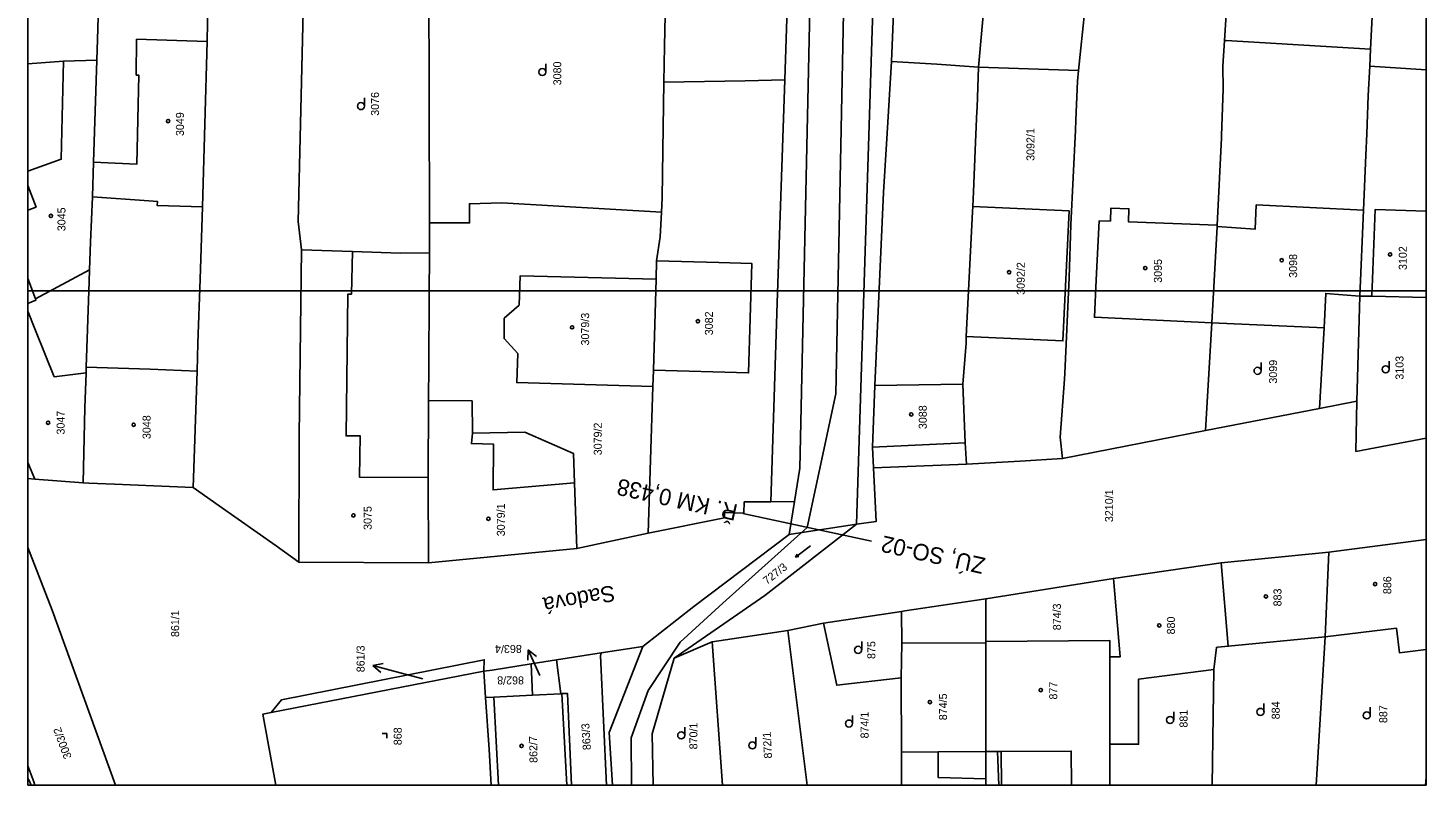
# Model space of a CAD drawing. Extents: x -534410 to -534262, y -1190162 to -1189584.
# Drawn here: x -534410.1 to -534261.6, y -1190162 to -1190081.5 of the extents above; entities that cross this region are included whole.
import ezdxf

# ---------------------------------------------------------------- set-up
doc = ezdxf.new("R2010")
doc.units = 0
for name, color, linetype in [('_KN_Povodí_Moravy', 7, 'Continuous'), ('_N_osa', 7, 'Continuous'), ('_N_tenká', 7, 'Continuous'), ('_N_text', 7, 'Continuous'), ('_rámeček', 7, 'Continuous'), ('_rámeček_mřížka', 7, 'Continuous'), ('_tenka', 7, 'Continuous'), ('Hranice parcel', 7, 'Continuous'), ('Parcelní čísla', 7, 'Continuous'), ('Polygon budovy', 7, 'Continuous'), ('Pop  PČ popisy', 7, 'Continuous'), ('Značky budov', 7, 'Continuous'), ('Značky kultur', 7, 'Continuous')]:
    doc.layers.add(name, color=color, linetype=linetype)

msp = doc.modelspace()

# ---------------------------------------------------------------- linework, layer by layer
at = {"layer": '_KN_Povodí_Moravy'}
for p, q in [((-534328.71, -1190131.86), (-534329.29, -1190135.36)), ((-534329.29, -1190135.36), (-534326.31, -1190134.9)), ((-534326.31, -1190134.9), (-534325.09, -1190134.72)), ((-534325.09, -1190134.72), (-534322.11, -1190134.26)), ((-534348.05, -1190161.97), (-534343.71, -1190161.97))]:
    msp.add_line(p, q, dxfattribs=at)
for points in [[(-534333.99, -1189993.03), (-534331.98, -1189997.67), (-534327.34, -1190013.08), (-534325.48, -1190021.81), (-534326.93, -1190073), (-534328.13, -1190128.3), (-534328.71, -1190131.86)], [(-534322.11, -1190134.26), (-534321.95, -1190128.7), (-534320.16, -1190072.85), (-534318.8, -1190033.53)], [(-534329.29, -1190135.36), (-534339.41, -1190143.01), (-534344.83, -1190147.24)], [(-534341.5, -1190148.5), (-534331.87, -1190141.82), (-534322.11, -1190134.26)], [(-534322.11, -1190134.26), (-534325.09, -1190134.72), (-534326.31, -1190134.9), (-534329.29, -1190135.36)], [(-534344.83, -1190147.24), (-534348.39, -1190156.38), (-534348.05, -1190161.97)], [(-534343.71, -1190161.97), (-534343.82, -1190156.54), (-534341.5, -1190148.5)]]:
    msp.add_lwpolyline(points, dxfattribs=at)
at = {"layer": '_N_osa'}
for points in [[(-534327.36, -1190134.6), (-534324.33, -1190120.41), (-534323.46, -1190078.16), (-534322.63, -1190051.74), (-534322.66, -1190021.45), (-534325.42, -1190005.39), (-534346.1, -1189954.57), (-534347.89, -1189950.33)], [(-534336.32, -1190142.64), (-534327.36, -1190134.6)], [(-534346.01, -1190161.97), (-534346.05, -1190156.96), (-534344.26, -1190151.93), (-534340.85, -1190146.78), (-534336.32, -1190142.64)]]:
    msp.add_lwpolyline(points, dxfattribs=at)
at = {"layer": '_N_tenká'}
msp.add_line((-534320.51, -1190136.06), (-534334.2, -1190133.14), dxfattribs=at)
at = {"layer": '_rámeček'}
msp.add_line((-534410.13, -1189584.47), (-534410.13, -1190161.97), dxfattribs=at)
msp.add_lwpolyline([(-534410.13, -1190161.97), (-534261.63, -1190161.97), (-534261.63, -1189584.47)], dxfattribs=at)
msp.add_lwpolyline([(-534410.13, -1190004.47), (-534261.63, -1190004.47), (-534261.63, -1190109.47), (-534410.13, -1190109.47)], close=True, dxfattribs=at)
at = {"layer": '_rámeček_mřížka'}
for p, q in [((-534410.13, -1189584.47), (-534410.13, -1190161.97)), ((-534407.13, -1190109.47), (-534410.13, -1190109.47)), ((-534264.63, -1190109.47), (-534261.63, -1190109.47))]:
    msp.add_line(p, q, dxfattribs=at)
msp.add_lwpolyline([(-534410.13, -1190161.97), (-534261.63, -1190161.97), (-534261.63, -1189584.47)], dxfattribs=at)
at = {"layer": '_tenka'}
for p, q in [((-534327.01, -1190136.55), (-534328.6, -1190137.78)), ((-534328.6, -1190137.78), (-534328.44, -1190137.45)), ((-534328.6, -1190137.78), (-534328.23, -1190137.71))]:
    msp.add_line(p, q, dxfattribs=at)
at = {"layer": 'Hranice parcel'}
for p, q in [((-534266.24, -1190056.9), (-534267.52, -1190083.79)), ((-534318.39, -1190085.1), (-534317.63, -1190065.52)), ((-534309.15, -1190085.72), (-534307.92, -1190071.47)), ((-534329.74, -1190087.07), (-534329.49, -1190079.46)), ((-534298.53, -1190086.06), (-534297.88, -1190079.61)), ((-534283.03, -1190082.87), (-534282.87, -1190080.13)), ((-534267.52, -1190083.79), (-534267.61, -1190085.62)), ((-534309.15, -1190085.72), (-534298.53, -1190086.06)), ((-534261.63, -1190086.01), (-534267.61, -1190085.62)), ((-534367.49, -1190105.45), (-534367.47, -1190102.26)), ((-534268.96, -1190121.2), (-534268.65, -1190110.03)), ((-534285.05, -1190124.32), (-534284.38, -1190112.87)), ((-534343.76, -1190119.63), (-534344.25, -1190135.21)), ((-534285.05, -1190124.32), (-534272.93, -1190121.97)), ((-534272.93, -1190121.97), (-534268.96, -1190121.2)), ((-534300.24, -1190127.27), (-534285.05, -1190124.32)), ((-534410.13, -1190127.69), (-534409.39, -1190129.48)), ((-534320.3, -1190128.29), (-534310.43, -1190127.9)), ((-534409.39, -1190129.48), (-534404.27, -1190129.87)), ((-534328.71, -1190131.86), (-534331.23, -1190131.88)), ((-534328.71, -1190131.86), (-534329.29, -1190135.36)), ((-534344.25, -1190135.21), (-534351.82, -1190136.86)), ((-534351.82, -1190136.86), (-534367.59, -1190138.36)), ((-534261.63, -1190135.89), (-534271.96, -1190137.25)), ((-534381.34, -1190138.28), (-534367.59, -1190138.36)), ((-534283.39, -1190138.38), (-534294.84, -1190140.02)), ((-534271.96, -1190137.25), (-534283.39, -1190138.38)), ((-534282.63, -1190147.23), (-534283.39, -1190138.38)), ((-534272.35, -1190146.24), (-534271.96, -1190137.25)), ((-534308.38, -1190142.18), (-534294.84, -1190140.02)), ((-534308.38, -1190142.18), (-534308.38, -1190146.73)), ((-534317.35, -1190143.53), (-534325.64, -1190144.79)), ((-534329.43, -1190145.56), (-534337.44, -1190146.76)), ((-534325.64, -1190144.79), (-534329.43, -1190145.56)), ((-534329.43, -1190145.56), (-534327.36, -1190161.97)), ((-534344.83, -1190147.24), (-534349.24, -1190147.93)), ((-534337.44, -1190146.76), (-534341.5, -1190148.5)), ((-534336.37, -1190161.97), (-534337.44, -1190146.76)), ((-534282.63, -1190147.23), (-534272.35, -1190146.24)), ((-534273.28, -1190161.97), (-534272.35, -1190146.24)), ((-534353.99, -1190148.68), (-534356.66, -1190149.1)), ((-534349.24, -1190147.93), (-534353.99, -1190148.68)), ((-534353.99, -1190148.68), (-534353.54, -1190152.27)), ((-534295.22, -1190157.63), (-534295.23, -1190148.36)), ((-534361.7, -1190149.89), (-534384.3, -1190154.28)), ((-534361.7, -1190149.89), (-534361.51, -1190152.68)), ((-534356.53, -1190152.42), (-534356.66, -1190149.1)), ((-534284.35, -1190161.97), (-534284.16, -1190149.68)), ((-534317.34, -1190158.47), (-534317.38, -1190150.59)), ((-534353.54, -1190152.27), (-534356.53, -1190152.42)), ((-534353.43, -1190152.26), (-534353.54, -1190152.27)), ((-534295.23, -1190161.97), (-534295.22, -1190157.63)), ((-534317.34, -1190161.97), (-534317.34, -1190158.47)), ((-534308.38, -1190158.41), (-534307.16, -1190158.4)), ((-534308.37, -1190161.3), (-534308.38, -1190158.41)), ((-534307.16, -1190158.4), (-534307.01, -1190161.97)), ((-534409.52, -1190161.62), (-534409.4, -1190161.97)), ((-534308.37, -1190161.97), (-534308.37, -1190161.3)), ((-534261.69, -1190161.97), (-534261.63, -1190161.16))]:
    msp.add_line(p, q, dxfattribs=at)
for points in [[(-534333.99, -1189993.03), (-534331.98, -1189997.67), (-534327.34, -1190013.08), (-534325.48, -1190021.81), (-534326.93, -1190073), (-534328.13, -1190128.3), (-534328.71, -1190131.86)], [(-534322.11, -1190134.26), (-534321.95, -1190128.7), (-534320.16, -1190072.85), (-534318.8, -1190033.53)], [(-534342.57, -1190087.3), (-534342.5, -1190083.48), (-534342.42, -1190078.52), (-534342.37, -1190071.42)], [(-534402.81, -1190084.96), (-534402.74, -1190082.76), (-534402.48, -1190074.44)], [(-534367.47, -1190102.26), (-534367.55, -1190076.15), (-534367.56, -1190073.35)], [(-534391.6, -1190100.55), (-534391.1, -1190082.99), (-534391.04, -1190081), (-534390.83, -1190074.99)], [(-534381.06, -1190105.11), (-534381.43, -1190102.09), (-534380.79, -1190075.34)], [(-534284.38, -1190112.87), (-534283.82, -1190102.63), (-534283.82, -1190102.51), (-534283.36, -1190093.22), (-534283.35, -1190093.02), (-534283.16, -1190088), (-534283.2, -1190085.62), (-534283.03, -1190082.87)], [(-534267.52, -1190083.79), (-534282.86, -1190082.88), (-534283.03, -1190082.87)], [(-534402.81, -1190084.96), (-534406.34, -1190085.09), (-534410.13, -1190085.36)], [(-534403.27, -1190099.48), (-534403.15, -1190095.8), (-534402.81, -1190084.96)], [(-534320.3, -1190128.29), (-534320.41, -1190126.09), (-534320.16, -1190119.52), (-534319.24, -1190099.01), (-534318.88, -1190092.72), (-534318.39, -1190085.1)], [(-534309.15, -1190085.72), (-534313.58, -1190085.41), (-534318.39, -1190085.1)], [(-534309.77, -1190100.51), (-534309.69, -1190098.95), (-534309.48, -1190093.67), (-534309.34, -1190090.37), (-534309.32, -1190090), (-534309.15, -1190085.72)], [(-534298.53, -1190086.06), (-534298.65, -1190087.21), (-534298.82, -1190091.33), (-534298.87, -1190092.42), (-534299.34, -1190102.45), (-534299.54, -1190108.06), (-534299.99, -1190118.24), (-534300.02, -1190118.87), (-534300.48, -1190125), (-534300.24, -1190127.27)], [(-534268.65, -1190110.03), (-534268.28, -1190100.92), (-534268.03, -1190095.07), (-534267.93, -1190092.81), (-534267.76, -1190088.71), (-534267.61, -1190085.62)], [(-534342.85, -1190101.1), (-534342.78, -1190099.6), (-534342.69, -1190094.55), (-534342.57, -1190087.3)], [(-534329.74, -1190087.07), (-534333.95, -1190087.15), (-534342.57, -1190087.3)], [(-534331.23, -1190131.88), (-534330.53, -1190110.76), (-534329.74, -1190087.07)], [(-534403.6, -1190107.23), (-534403.48, -1190104.31), (-534403.27, -1190099.48)], [(-534391.6, -1190100.55), (-534396.4, -1190100.41), (-534396.37, -1190099.97), (-534397.3, -1190099.9), (-534403.27, -1190099.48)], [(-534392.57, -1190130.35), (-534392.17, -1190117.99), (-534392.07, -1190115.02), (-534391.85, -1190108.23), (-534391.6, -1190100.55)], [(-534367.47, -1190102.26), (-534363.21, -1190102.26), (-534363.24, -1190100.22), (-534359.78, -1190100.14), (-534342.85, -1190101.1)], [(-534342.85, -1190101.1), (-534342.97, -1190103.75), (-534343.35, -1190106.28), (-534343.41, -1190108.25)], [(-534310.46, -1190114.33), (-534309.8, -1190101.09), (-534309.77, -1190100.51)], [(-534309.77, -1190100.51), (-534299.54, -1190100.99), (-534300.2, -1190114.79), (-534310.46, -1190114.33)], [(-534381.34, -1190138.28), (-534381.33, -1190124.85), (-534381.06, -1190105.11)], [(-534367.49, -1190105.45), (-534370.56, -1190105.46), (-534375.64, -1190105.3), (-534381.06, -1190105.11)], [(-534367.57, -1190121.12), (-534367.57, -1190120.94), (-534367.55, -1190117.44), (-534367.51, -1190110.01), (-534367.49, -1190105.45)], [(-534410.13, -1190110.83), (-534409.28, -1190110.45), (-534409.33, -1190110.33), (-534403.6, -1190107.23)], [(-534404.27, -1190129.87), (-534404.08, -1190121.91), (-534403.96, -1190118.2), (-534403.94, -1190117.57), (-534403.64, -1190108.48), (-534403.6, -1190107.23)], [(-534343.41, -1190108.25), (-534357.86, -1190107.88), (-534357.95, -1190110.98), (-534359.56, -1190112.38), (-534359.55, -1190114.54), (-534358.11, -1190116.13), (-534358.2, -1190119.22), (-534343.76, -1190119.63)], [(-534343.41, -1190108.25), (-534343.7, -1190117.89), (-534343.76, -1190119.63)], [(-534268.65, -1190110.03), (-534267.38, -1190110.05), (-534261.63, -1190110.19)], [(-534284.38, -1190112.87), (-534272.46, -1190113.39), (-534272.93, -1190121.97)], [(-534310.43, -1190127.9), (-534310.57, -1190125.63), (-534310.83, -1190119.37), (-534310.49, -1190115.03), (-534310.46, -1190114.33)], [(-534367.59, -1190138.36), (-534367.61, -1190129.31), (-534367.57, -1190121.12)], [(-534351.82, -1190136.86), (-534352.07, -1190129.87), (-534352.17, -1190126.76), (-534357.34, -1190124.5), (-534362.92, -1190124.6), (-534362.95, -1190121.17), (-534367.57, -1190121.12)], [(-534268.96, -1190121.2), (-534269.07, -1190126.53), (-534261.63, -1190125.12)], [(-534300.24, -1190127.27), (-534304.74, -1190127.55), (-534310.43, -1190127.9)], [(-534409.39, -1190129.48), (-534410.13, -1190129.42)], [(-534322.11, -1190134.26), (-534320.02, -1190133.96), (-534320.3, -1190128.29)], [(-534404.27, -1190129.87), (-534403.67, -1190129.9), (-534400.93, -1190130.01), (-534392.57, -1190130.35)], [(-534392.57, -1190130.35), (-534389.82, -1190132.3), (-534383.78, -1190136.56), (-534381.34, -1190138.28)], [(-534344.25, -1190135.21), (-534336.14, -1190133.57), (-534336.13, -1190133.02), (-534334.08, -1190133.08), (-534334.05, -1190131.9), (-534331.23, -1190131.88)], [(-534344.83, -1190147.24), (-534339.41, -1190143.01), (-534329.29, -1190135.36)], [(-534322.11, -1190134.26), (-534331.87, -1190141.82), (-534341.5, -1190148.5)], [(-534329.29, -1190135.36), (-534326.31, -1190134.9), (-534325.09, -1190134.72), (-534322.11, -1190134.26)], [(-534410.13, -1190136.74), (-534407.57, -1190143.38), (-534400.84, -1190161.97)], [(-534295.23, -1190148.36), (-534294.11, -1190148.35), (-534294.84, -1190140.02)], [(-534308.38, -1190142.18), (-534316.97, -1190143.47), (-534317.35, -1190143.53)], [(-534317.35, -1190143.53), (-534317.32, -1190146.91), (-534317.38, -1190150.59)], [(-534317.38, -1190150.59), (-534324.22, -1190151.37), (-534325.64, -1190144.79)], [(-534272.35, -1190146.24), (-534264.78, -1190145.3), (-534264.45, -1190147.91), (-534261.63, -1190147.56)], [(-534348.05, -1190161.97), (-534348.39, -1190156.38), (-534344.83, -1190147.24)], [(-534308.38, -1190146.73), (-534295.23, -1190146.6), (-534295.23, -1190148.36)], [(-534308.38, -1190158.41), (-534308.38, -1190146.85), (-534308.38, -1190146.73)], [(-534284.16, -1190149.68), (-534283.89, -1190147.35), (-534283.74, -1190147.34), (-534282.63, -1190147.23)], [(-534384.3, -1190154.28), (-534383.2, -1190152.93), (-534361.66, -1190148.66), (-534361.7, -1190149.89)], [(-534349.24, -1190147.93), (-534349.33, -1190148.26), (-534348.69, -1190161.97)], [(-534341.5, -1190148.5), (-534343.82, -1190156.54), (-534343.71, -1190161.97)], [(-534356.66, -1190149.1), (-534360.81, -1190149.75), (-534361.7, -1190149.89)], [(-534295.22, -1190157.63), (-534292.16, -1190157.63), (-534292.17, -1190150.74), (-534284.16, -1190149.68)], [(-534356.53, -1190152.42), (-534360.66, -1190152.64), (-534361.51, -1190152.68)], [(-534361.51, -1190152.68), (-534361.14, -1190158.2), (-534360.93, -1190161.97)], [(-534353.43, -1190152.26), (-534352.82, -1190152.23), (-534352.39, -1190161.97)], [(-534352.9, -1190161.97), (-534353.43, -1190152.26)], [(-534384.3, -1190154.28), (-534385.19, -1190154.45), (-534383.81, -1190161.97)], [(-534308.37, -1190161.3), (-534313.43, -1190161.17), (-534313.45, -1190158.44), (-534317.34, -1190158.47)], [(-534307.16, -1190158.4), (-534306.75, -1190158.4), (-534306.71, -1190161.97)], [(-534410.13, -1190159.94), (-534409.52, -1190161.62)], [(-534410.13, -1190161.27), (-534410.04, -1190161.42), (-534409.79, -1190161.97)]]:
    msp.add_lwpolyline(points, dxfattribs=at)
at = {"layer": 'Polygon budovy'}
for p, q in [((-534410.13, -1190096.76), (-534410.13, -1190098.28)), ((-534410.13, -1190100.91), (-534410.13, -1190108.15)), ((-534261.63, -1190110.19), (-534261.63, -1190101.01)), ((-534410.13, -1190111.64), (-534410.13, -1190127.69)), ((-534261.63, -1190147.56), (-534261.63, -1190135.89)), ((-534360.15, -1190161.97), (-534352.9, -1190161.97)), ((-534299.3, -1190161.97), (-534295.23, -1190161.97))]:
    msp.add_line(p, q, dxfattribs=at)
for points in [[(-534398.59, -1190082.73), (-534398.63, -1190086.56), (-534398.35, -1190086.56), (-534398.56, -1190096.01), (-534403.15, -1190095.8), (-534403.27, -1190099.48), (-534397.3, -1190099.9), (-534396.37, -1190099.97), (-534396.4, -1190100.41), (-534391.6, -1190100.55), (-534391.1, -1190082.99)], [(-534300.2, -1190114.79), (-534299.54, -1190100.99), (-534309.77, -1190100.51), (-534309.8, -1190101.09), (-534310.46, -1190114.33)], [(-534284.38, -1190112.87), (-534283.82, -1190102.63), (-534283.82, -1190102.51), (-534293.24, -1190102.14), (-534293.19, -1190100.76), (-534295.09, -1190100.69), (-534295.15, -1190102.06), (-534296.34, -1190102.02), (-534296.65, -1190108.29), (-534296.85, -1190112.27)], [(-534279.66, -1190100.35), (-534279.78, -1190102.93), (-534283.82, -1190102.63), (-534284.38, -1190112.87), (-534272.46, -1190113.39), (-534272.27, -1190109.75), (-534268.65, -1190110.03), (-534268.28, -1190100.92)], [(-534381.34, -1190138.28), (-534367.59, -1190138.36), (-534367.61, -1190129.31), (-534374.9, -1190129.27), (-534374.84, -1190124.88), (-534376.33, -1190124.88), (-534376.16, -1190109.83), (-534375.77, -1190109.83), (-534375.64, -1190105.3), (-534381.06, -1190105.11), (-534381.33, -1190124.85)], [(-534336.76, -1190106.48), (-534343.35, -1190106.28), (-534343.41, -1190108.25), (-534343.7, -1190117.89), (-534333.58, -1190118.2), (-534333.23, -1190106.58)], [(-534343.7, -1190117.89), (-534343.41, -1190108.25), (-534357.86, -1190107.88), (-534357.95, -1190110.98), (-534359.56, -1190112.38), (-534359.55, -1190114.54), (-534358.11, -1190116.13), (-534358.2, -1190119.22), (-534343.76, -1190119.63)], [(-534392.57, -1190130.35), (-534392.17, -1190117.99), (-534397.14, -1190117.81), (-534403.94, -1190117.57), (-534403.96, -1190118.2), (-534404.08, -1190121.91), (-534404.27, -1190129.87), (-534403.67, -1190129.9), (-534400.93, -1190130.01)], [(-534310.83, -1190119.37), (-534320.16, -1190119.52), (-534320.41, -1190126.09), (-534310.57, -1190125.63)], [(-534351.82, -1190136.86), (-534352.07, -1190129.87), (-534360.72, -1190130.62), (-534360.69, -1190125.75), (-534363.02, -1190125.69), (-534362.92, -1190124.6), (-534362.95, -1190121.17), (-534367.57, -1190121.12), (-534367.61, -1190129.31), (-534367.59, -1190138.36)], [(-534295.23, -1190148.36), (-534295.22, -1190157.63), (-534292.16, -1190157.63), (-534292.17, -1190150.74), (-534284.16, -1190149.68), (-534283.89, -1190147.35), (-534283.74, -1190147.34), (-534282.63, -1190147.23), (-534283.39, -1190138.38), (-534294.84, -1190140.02), (-534294.11, -1190148.35)], [(-534283.39, -1190138.38), (-534282.63, -1190147.23), (-534272.35, -1190146.24), (-534271.96, -1190137.25)], [(-534317.38, -1190150.59), (-534317.34, -1190158.47), (-534313.45, -1190158.44), (-534308.38, -1190158.41), (-534308.38, -1190146.85), (-534317.32, -1190146.91)]]:
    msp.add_lwpolyline(points, close=True, dxfattribs=at)
for points in [[(-534410.13, -1190108.15), (-534409.33, -1190110.33), (-534403.6, -1190107.23), (-534403.48, -1190104.31), (-534403.27, -1190099.48), (-534403.15, -1190095.8), (-534402.81, -1190084.96), (-534406.34, -1190085.09), (-534406.59, -1190095.5), (-534410.13, -1190096.76)], [(-534410.13, -1190098.28), (-534409.26, -1190100.57), (-534410.13, -1190100.91)], [(-534261.63, -1190101.01), (-534267.04, -1190100.85), (-534267.38, -1190110.05), (-534261.63, -1190110.19)], [(-534410.13, -1190127.69), (-534409.39, -1190129.48), (-534404.27, -1190129.87), (-534404.08, -1190121.91), (-534403.96, -1190118.2), (-534407.34, -1190118.6), (-534409.31, -1190113.68), (-534410.13, -1190111.64)], [(-534261.63, -1190135.89), (-534271.96, -1190137.25), (-534272.35, -1190146.24), (-534264.78, -1190145.3), (-534264.45, -1190147.91), (-534261.63, -1190147.56)], [(-534295.23, -1190161.97), (-534295.22, -1190157.63), (-534295.23, -1190148.36), (-534295.23, -1190146.6), (-534308.38, -1190146.73), (-534308.38, -1190146.85), (-534308.38, -1190158.41), (-534307.16, -1190158.4), (-534306.75, -1190158.4), (-534299.31, -1190158.37), (-534299.3, -1190161.97)], [(-534352.9, -1190161.97), (-534353.43, -1190152.26), (-534353.54, -1190152.27), (-534356.53, -1190152.42), (-534360.66, -1190152.64), (-534360.15, -1190161.97)]]:
    msp.add_lwpolyline(points, dxfattribs=at)
at = {"layer": 'Pop  PČ popisy'}
for p, q in [((-534356.99, -1190147.59), (-534357.04, -1190148.7)), ((-534355.77, -1190150.33), (-534356.99, -1190147.59)), ((-534356.99, -1190147.59), (-534356.12, -1190148.3)), ((-534373.5, -1190149.27), (-534372.4, -1190149.05)), ((-534370.6, -1190150.05), (-534373.5, -1190149.27)), ((-534373.5, -1190149.27), (-534372.66, -1190150.02)), ((-534368.19, -1190150.7), (-534370.6, -1190150.05))]:
    msp.add_line(p, q, dxfattribs=at)
at = {"layer": 'Značky budov'}
for centre in [(-534395.24, -1190091.44), (-534407.69, -1190101.52), (-534265.44, -1190105.61), (-534291.45, -1190107.06), (-534276.96, -1190106.23), (-534305.91, -1190107.5), (-534338.97, -1190112.71), (-534352.33, -1190113.35), (-534407.99, -1190123.48), (-534398.9, -1190123.7), (-534316.3, -1190122.6), (-534375.55, -1190133.33), (-534361.21, -1190133.69), (-534267.03, -1190140.62), (-534278.64, -1190141.94), (-534289.96, -1190145.01), (-534302.55, -1190151.88), (-534314.32, -1190153.16), (-534357.7, -1190157.81)]:
    msp.add_circle(centre, 0.175, dxfattribs=at)
at = {"layer": 'Značky kultur'}
for p, q in [((-534355.12, -1190086.23), (-534355.12, -1190085.35)), ((-534374.38, -1190089.85), (-534374.38, -1190088.97)), ((-534279.15, -1190117.97), (-534279.15, -1190117.1)), ((-534265.53, -1190117.81), (-534265.53, -1190116.93)), ((-534321.57, -1190147.61), (-534321.57, -1190146.73)), ((-534322.55, -1190155.44), (-534322.55, -1190154.57)), ((-534288.43, -1190155.06), (-534288.43, -1190154.19)), ((-534278.84, -1190154.2), (-534278.84, -1190153.32)), ((-534267.55, -1190154.57), (-534267.55, -1190153.69)), ((-534340.37, -1190156.69), (-534340.37, -1190155.82)), ((-534372, -1190156.48), (-534372.5, -1190156.48)), ((-534372, -1190156.98), (-534372, -1190156.48)), ((-534332.81, -1190157.76), (-534332.81, -1190156.89))]:
    msp.add_line(p, q, dxfattribs=at)
for centre in [(-534355.49, -1190086.23), (-534374.76, -1190089.85), (-534279.52, -1190117.97), (-534265.91, -1190117.81), (-534321.95, -1190147.61), (-534288.81, -1190155.06), (-534279.21, -1190154.2), (-534267.92, -1190154.57), (-534322.92, -1190155.44), (-534340.74, -1190156.69), (-534333.18, -1190157.76)]:
    msp.add_circle(centre, 0.375, dxfattribs=at)

# ---------------------------------------------------------------- texts
at = {"layer": '_N_text'}
for s, p in [('Ř. KM 0,438', (-534334.63, -1190132.21)), ('ZÚ, SO-02', (-534308.34, -1190137.87))]:
    msp.add_text(s, height=1.75, rotation=167.5017, dxfattribs=at).set_placement(p)
at = {"layer": '_tenka'}
msp.add_text('727/3', height=0.85, rotation=37.8364, dxfattribs=at).set_placement((-534331.64, -1190140.72))
at = {"layer": 'Parcelní čísla'}
for s, rotation, p in [('3080', 90, (-534353.48, -1190087.64)), ('3076', 90, (-534372.84, -1190090.88)), ('3049', 90, (-534393.56, -1190093.03)), ('3092/1', 90, (-534303.22, -1190095.67)), ('3045', 90, (-534406.14, -1190103.14)), ('3098', 90, (-534275.32, -1190108.09)), ('3102', 90, (-534263.67, -1190107.26)), ('3092/2', 90, (-534304.25, -1190109.9)), ('3095', 90, (-534289.68, -1190108.62)), ('3079/3', 90, (-534350.52, -1190115.28)), ('3082', 90, (-534337.37, -1190114.19)), ('3099', 90, (-534277.45, -1190119.33)), ('3103', 90, (-534264.02, -1190118.91)), ('3088', 90, (-534314.66, -1190124.16)), ('3047', 90, (-534406.23, -1190124.74)), ('3048', 90, (-534397.1, -1190125.22)), ('3079/2', 90, (-534349.18, -1190126.94)), ('3210/1', 90, (-534294.87, -1190134.04)), ('3075', 90, (-534373.62, -1190134.87)), ('3079/1', 90, (-534359.47, -1190135.54)), ('886', 90, (-534265.32, -1190141.69)), ('883', 90, (-534276.98, -1190142.99)), ('874/3', 90, (-534300.41, -1190145.53)), ('861/1', 90, (-534394.07, -1190146.25)), ('880', 90, (-534288.3, -1190145.97)), ('861/3', 90, (-534374.37, -1190149.99)), ('863/4', 180, (-534357.67, -1190147.09)), ('875', 90, (-534320.12, -1190148.58)), ('862/8', 180, (-534357.44, -1190150.43)), ('877', 90, (-534300.8, -1190152.89)), ('874/5', 90, (-534312.51, -1190155.09)), ('884', 90, (-534277.17, -1190154.99)), ('874/1', 90, (-534320.84, -1190157.02)), ('881', 90, (-534286.96, -1190155.87)), ('887', 90, (-534265.75, -1190155.39)), ('3003/2', 110.3929, (-534405.46, -1190159.01)), ('868', 90, (-534370.43, -1190157.74)), ('863/3', 93.6145, (-534350.33, -1190158.23)), ('870/1', 90, (-534339.02, -1190158.18)), ('862/7', 91, (-534356, -1190159.61)), ('872/1', 93, (-534331.09, -1190159.13))]:
    msp.add_text(s, height=0.85, rotation=rotation, dxfattribs=at).set_placement(p)
at = {"layer": 'Pop  PČ popisy'}
msp.add_text('Sadová', height=1.7, rotation=190.1952, dxfattribs=at).set_placement((-534347.94, -1190140.72))

doc.saveas('drawing.dxf')
